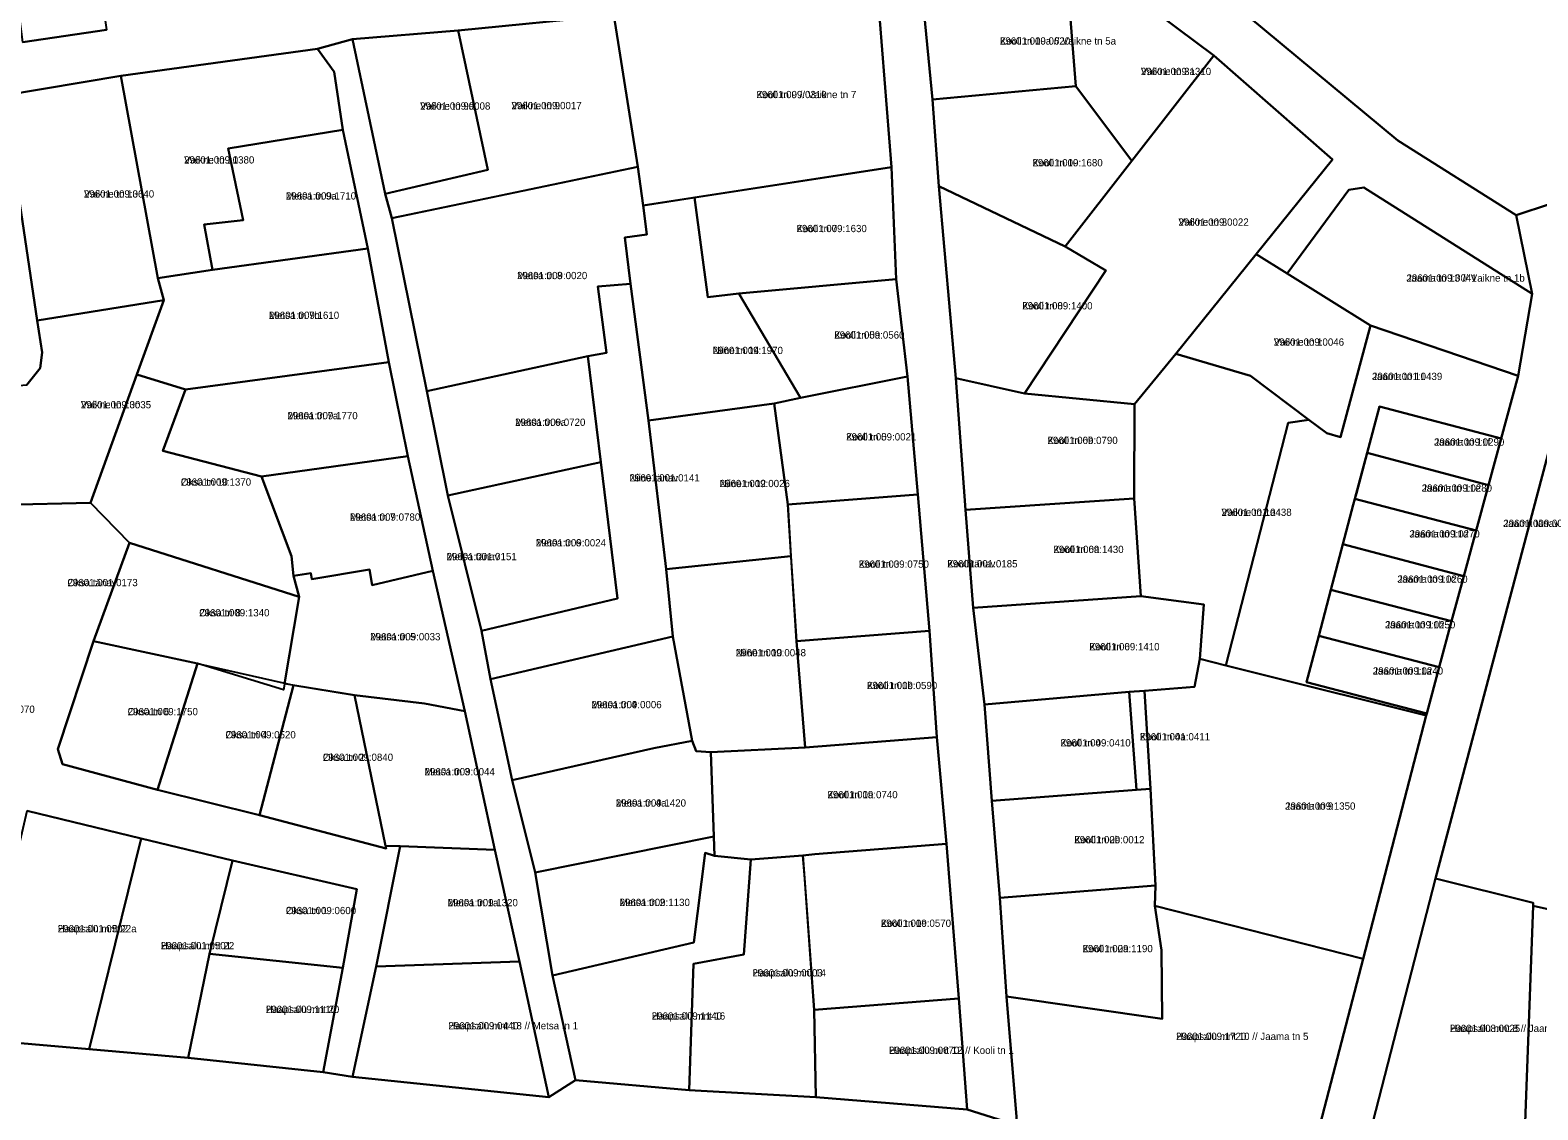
# Model space of a CAD drawing. Extents: x 518839 to 525192, y 6573164 to 6576561.
# Drawn here: x 523365.3 to 523676.7, y 6574443.2 to 6574666.3 of the extents above; entities that cross this region are included whole.
import ezdxf

# ---------------------------------------------------------------- set-up
doc = ezdxf.new("R2010")
doc.units = 0
for name, color, linetype in [('L_AADRESS', 7, 'Continuous'), ('PIIR', 7, 'Continuous'), ('TUNNUS', 7, 'Continuous')]:
    doc.layers.add(name, color=color, linetype=linetype)

msp = doc.modelspace()

# ---------------------------------------------------------------- linework, layer by layer
at = {"layer": 'PIIR'}
for points in [[(523615.35, 6574742.57), (523654.8, 6574704.19), (523668.48, 6574686.53), (523689.46, 6574680.22), (523679.3, 6574630.35), (523672.22, 6574628.03), (523647.77, 6574643.48), (523599.55, 6574683.56), (523607.36, 6574715.71), (523613.69, 6574736.97)], [(523700.2, 6574721.72), (523710.02, 6574696.46), (523687.1, 6574608.01), (523679.27, 6574581.95), (523679.09, 6574579.83), (523655.53, 6574491), (523641.32, 6574435.85), (523645.97, 6574429.03), (523629.03, 6574429.92), (523640.58, 6574474.42), (523653.58, 6574524.69), (523653.71, 6574525.12), (523656.28, 6574534.68), (523658.83, 6574544.16), (523661.39, 6574553.49), (523663.93, 6574562.87), (523666.49, 6574572.3), (523669.1, 6574581.93), (523672.63, 6574594.87), (523675.51, 6574611.76), (523672.22, 6574628.03), (523679.3, 6574630.35), (523689.46, 6574680.22)], [(523371.76, 6574716.56), (523372.55, 6574716.47), (523377.4, 6574692.22), (523381.14, 6574666.32), (523363.81, 6574663.75), (523360.45, 6574690.27), (523354.26, 6574689.99), (523350.61, 6574714.52)], [(523490.79, 6574637.99), (523485.85, 6574669.33), (523540.34, 6574674.35), (523543.19, 6574637.93), (523491.91, 6574630.07)], [(523543.19, 6574637.93), (523540.34, 6574674.35), (523549.77, 6574671.85), (523551.7, 6574651.94), (523552.95, 6574634.06), (523556.48, 6574594.4), (523558.48, 6574567.15), (523560.09, 6574546.96), (523562.38, 6574526.98), (523563.91, 6574507.04), (523565.54, 6574487.01), (523566.98, 6574466.62), (523568.99, 6574441.81), (523569.1, 6574440.03), (523558.83, 6574443.32), (523557.1, 6574466.25), (523554.58, 6574498.15), (523552.58, 6574520.23), (523551.05, 6574542.17), (523548.62, 6574570.34), (523546.53, 6574594.73), (523544.14, 6574614.8)], [(523549.77, 6574671.85), (523579.65, 6574674.61), (523581.29, 6574654.66), (523551.7, 6574651.94)], [(523579.65, 6574674.61), (523590.58, 6574675.41), (523609.74, 6574661.03), (523592.83, 6574639.23), (523586.78, 6574647.32), (523581.29, 6574654.66)], [(523485.85, 6574669.33), (523490.79, 6574637.99), (523461.21, 6574631.85), (523440.01, 6574627.45), (523438.68, 6574632.46), (523459.85, 6574637.41), (523453.75, 6574666.2)], [(523428.15, 6574657.65), (523424.7, 6574662.39), (523431.88, 6574664.38), (523438.68, 6574632.46), (523440.01, 6574627.45), (523447.24, 6574591.66), (523451.59, 6574570.1), (523458.52, 6574542.21), (523460.38, 6574532.19), (523464.9, 6574511.35), (523469.61, 6574492.27), (523473.22, 6574470.97), (523477.93, 6574449.33), (523472.47, 6574445.83), (523466.39, 6574473.87), (523461.27, 6574496.95), (523455.09, 6574525.6), (523448.46, 6574554.54), (523443.35, 6574578.26), (523439.4, 6574597.7), (523435.05, 6574621.16), (523429.94, 6574645.64)], [(523438.68, 6574632.46), (523431.88, 6574664.38), (523453.75, 6574666.2), (523459.85, 6574637.41)], [(523424.7, 6574662.39), (523428.15, 6574657.65), (523429.94, 6574645.64), (523406.24, 6574641.78), (523409.33, 6574627), (523401.26, 6574626.1), (523402.98, 6574616.72), (523391.71, 6574615.04), (523384.07, 6574656.83)], [(523634.25, 6574639.55), (523618.49, 6574619.99), (523601.94, 6574599.41), (523593.37, 6574589.02), (523570.68, 6574591.23), (523587.46, 6574616.6), (523579.04, 6574621.57), (523592.83, 6574639.23), (523609.74, 6574661.03)], [(523384.07, 6574656.83), (523391.71, 6574615.04), (523392.97, 6574610.47), (523366.8, 6574606.26), (523359.93, 6574652.76)], [(523551.7, 6574651.94), (523581.29, 6574654.66), (523586.78, 6574647.32), (523592.83, 6574639.23), (523579.04, 6574621.57), (523552.95, 6574634.06)], [(523401.26, 6574626.1), (523409.33, 6574627), (523406.24, 6574641.78), (523429.94, 6574645.64), (523435.05, 6574621.16), (523402.98, 6574616.72)], [(523440.01, 6574627.45), (523490.79, 6574637.99), (523491.91, 6574630.07), (523492.66, 6574624.04), (523488.16, 6574623.45), (523489.32, 6574613.87), (523482.55, 6574613.28), (523484.36, 6574599.61), (523480.52, 6574598.93), (523447.24, 6574591.66)], [(523544.14, 6574614.8), (523511.65, 6574611.85), (523505.28, 6574611.13), (523502.5, 6574631.69), (523543.19, 6574637.93)], [(523552.95, 6574634.06), (523579.04, 6574621.57), (523587.46, 6574616.6), (523570.68, 6574591.23), (523556.48, 6574594.4)], [(523624.92, 6574615.99), (523637.63, 6574633.25), (523640.7, 6574633.75), (523675.51, 6574611.76), (523672.63, 6574594.87), (523642.14, 6574605.25)], [(523489.32, 6574613.87), (523488.16, 6574623.45), (523492.66, 6574624.04), (523491.91, 6574630.07), (523502.5, 6574631.69), (523505.28, 6574611.13), (523511.65, 6574611.85), (523524.41, 6574590.29), (523518.94, 6574589.17), (523493, 6574585.65)], [(523439.4, 6574597.7), (523397.42, 6574592.05), (523387.38, 6574595.16), (523392.97, 6574610.47), (523391.71, 6574615.04), (523402.98, 6574616.72), (523435.05, 6574621.16)], [(523618.49, 6574619.99), (523624.92, 6574615.99), (523642.14, 6574605.25), (523635.91, 6574582.17), (523633.09, 6574583.01), (523629.38, 6574585.75), (523617.33, 6574594.83), (523601.94, 6574599.41)], [(523484.36, 6574599.61), (523482.55, 6574613.28), (523489.32, 6574613.87), (523493, 6574585.65), (523496.69, 6574554.93), (523498.08, 6574541.03), (523460.38, 6574532.19), (523458.52, 6574542.21), (523486.6, 6574548.87), (523483.21, 6574577.03), (523480.52, 6574598.93)], [(523524.41, 6574590.29), (523511.65, 6574611.85), (523544.14, 6574614.8), (523546.53, 6574594.73)], [(523366.8, 6574606.26), (523392.97, 6574610.47), (523387.38, 6574595.16), (523377.83, 6574568.61), (523360.01, 6574568.22), (523358.68, 6574586.91), (523360.51, 6574592.67), (523364.67, 6574593.01), (523367.38, 6574596.44), (523367.82, 6574599.7)], [(523625.11, 6574585.12), (523629.38, 6574585.75), (523633.09, 6574583.01), (523635.91, 6574582.17), (523642.14, 6574605.25), (523672.63, 6574594.87), (523669.1, 6574581.93), (523643.95, 6574588.55), (523641.4, 6574578.96), (523639.21, 6574570.61), (523638.89, 6574569.43), (523638.54, 6574568.17), (523636.4, 6574560.05), (523633.93, 6574550.67), (523631.42, 6574541.17), (523628.92, 6574531.57), (523653.71, 6574525.12), (523653.58, 6574524.69), (523618.59, 6574533.4), (523612.23, 6574535)], [(523447.24, 6574591.66), (523480.52, 6574598.93), (523483.21, 6574577.03), (523451.59, 6574570.1)], [(523593.37, 6574589.02), (523601.94, 6574599.41), (523617.33, 6574594.83), (523629.38, 6574585.75), (523625.11, 6574585.12), (523612.23, 6574535), (523606.86, 6574536.39), (523607.72, 6574547.61), (523594.71, 6574549.33), (523593.28, 6574569.54)], [(523377.83, 6574568.61), (523387.38, 6574595.16), (523397.42, 6574592.05), (523392.72, 6574579.39), (523413.12, 6574574.05), (523419.31, 6574557.59), (523419.75, 6574553.51), (523420.88, 6574549.17), (523385.87, 6574560.33)], [(523392.72, 6574579.39), (523397.42, 6574592.05), (523439.4, 6574597.7), (523443.35, 6574578.26), (523413.12, 6574574.05)], [(523548.62, 6574570.34), (523521.82, 6574568.26), (523518.94, 6574589.17), (523524.41, 6574590.29), (523546.53, 6574594.73)], [(523570.68, 6574591.23), (523593.37, 6574589.02), (523593.28, 6574569.54), (523558.48, 6574567.15), (523556.48, 6574594.4)], [(523493, 6574585.65), (523518.94, 6574589.17), (523521.82, 6574568.26), (523522.44, 6574557.62), (523496.69, 6574554.93)], [(523641.4, 6574578.96), (523643.95, 6574588.55), (523669.1, 6574581.93), (523666.49, 6574572.3)], [(523679.09, 6574579.83), (523715.18, 6574570.22), (523730.41, 6574491.16), (523690.47, 6574482.07), (523675.73, 6574485.36), (523675.69, 6574485.98), (523655.53, 6574491)], [(523413.12, 6574574.05), (523443.35, 6574578.26), (523448.46, 6574554.54), (523435.97, 6574551.59), (523435.39, 6574554.83), (523423.52, 6574552.87), (523423.32, 6574554.1), (523419.75, 6574553.51), (523419.31, 6574557.59)], [(523483.21, 6574577.03), (523486.6, 6574548.87), (523458.52, 6574542.21), (523451.59, 6574570.1)], [(523638.89, 6574569.43), (523641.4, 6574578.96), (523666.49, 6574572.3), (523663.93, 6574562.87)], [(523521.82, 6574568.26), (523548.62, 6574570.34), (523551.05, 6574542.17), (523523.56, 6574540.02)], [(523593.28, 6574569.54), (523594.71, 6574549.33), (523560.09, 6574546.96), (523558.48, 6574567.15)], [(523636.4, 6574560.05), (523638.54, 6574568.17), (523638.89, 6574569.43), (523663.93, 6574562.87), (523661.39, 6574553.49)], [(523420.88, 6574549.17), (523417.69, 6574530.02), (523399.88, 6574535.41), (523378.41, 6574540.03), (523385.87, 6574560.33)], [(523633.93, 6574550.67), (523636.4, 6574560.05), (523661.39, 6574553.49), (523658.83, 6574544.16)], [(523419.75, 6574553.51), (523423.32, 6574554.1), (523423.52, 6574552.87), (523435.39, 6574554.83), (523435.97, 6574551.59), (523448.46, 6574554.54), (523455.09, 6574525.6), (523446.8, 6574527.14), (523432.3, 6574528.91), (523417.89, 6574531.25), (523420.88, 6574549.17)], [(523522.44, 6574557.62), (523523.56, 6574540.02), (523525.39, 6574518.1), (523505.9, 6574517.13), (523502.87, 6574517.3), (523502.02, 6574519.47), (523498.08, 6574541.03), (523496.69, 6574554.93)], [(523560.09, 6574546.96), (523594.71, 6574549.33), (523607.72, 6574547.61), (523606.86, 6574536.39), (523605.79, 6574530.64), (523595.41, 6574529.79), (523592.27, 6574529.55), (523562.38, 6574526.98)], [(523631.42, 6574541.17), (523633.93, 6574550.67), (523658.83, 6574544.16), (523656.28, 6574534.68)], [(523523.56, 6574540.02), (523551.05, 6574542.17), (523552.58, 6574520.23), (523525.39, 6574518.1)], [(523399.88, 6574535.41), (523391.65, 6574509.31), (523372.04, 6574514.61), (523371.07, 6574517.7), (523378.41, 6574540.03)], [(523460.38, 6574532.19), (523498.08, 6574541.03), (523502.02, 6574519.47), (523494.16, 6574517.95), (523464.9, 6574511.35)], [(523628.92, 6574531.57), (523631.42, 6574541.17), (523656.28, 6574534.68), (523653.71, 6574525.12)], [(523605.79, 6574530.64), (523606.86, 6574536.39), (523612.23, 6574535), (523618.59, 6574533.4), (523653.58, 6574524.69), (523640.58, 6574474.42), (523597.61, 6574485.39), (523597.69, 6574489.54), (523596.69, 6574509.56), (523595.41, 6574529.79)], [(523419.73, 6574530.95), (523412.71, 6574504.1), (523391.65, 6574509.31), (523399.88, 6574535.41)], [(523432.3, 6574528.91), (523438.75, 6574497.74), (523438.86, 6574497.2), (523412.71, 6574504.1), (523419.73, 6574530.95)], [(523593.82, 6574509.34), (523592.27, 6574529.55), (523595.41, 6574529.79), (523596.69, 6574509.56)], [(523432.3, 6574528.91), (523446.8, 6574527.14), (523455.09, 6574525.6), (523461.27, 6574496.95), (523441.74, 6574497.71), (523438.75, 6574497.74)], [(523562.38, 6574526.98), (523592.27, 6574529.55), (523593.82, 6574509.34), (523563.91, 6574507.04)], [(523464.9, 6574511.35), (523494.16, 6574517.95), (523502.02, 6574519.47), (523502.87, 6574517.3), (523505.9, 6574517.13), (523506.49, 6574499.69), (523469.61, 6574492.27)], [(523514.19, 6574494.95), (523506.63, 6574495.69), (523506.49, 6574499.69), (523505.9, 6574517.13), (523525.39, 6574518.1), (523552.58, 6574520.23), (523554.58, 6574498.15), (523527.4, 6574496.01), (523524.91, 6574495.74)], [(523563.91, 6574507.04), (523593.82, 6574509.34), (523596.69, 6574509.56), (523597.69, 6574489.54), (523565.54, 6574487.01)], [(523353.78, 6574457.82), (523364.71, 6574505), (523388.29, 6574499.29), (523377.5, 6574455.78)], [(523377.5, 6574455.78), (523388.29, 6574499.29), (523407.15, 6574494.73), (523402.4, 6574475.46), (523397.99, 6574454)], [(523469.61, 6574492.27), (523506.49, 6574499.69), (523506.63, 6574495.69), (523504.73, 6574496.33), (523502.4, 6574477.82), (523473.22, 6574470.97)], [(523436.76, 6574472.84), (523441.74, 6574497.71), (523461.27, 6574496.95), (523466.39, 6574473.87)], [(523473.22, 6574470.97), (523502.4, 6574477.82), (523504.73, 6574496.33), (523506.63, 6574495.69), (523514.19, 6574494.95), (523512.73, 6574475.34), (523502.3, 6574473.42), (523501.43, 6574447.28), (523477.93, 6574449.33)], [(523502.3, 6574473.42), (523512.73, 6574475.34), (523514.19, 6574494.95), (523524.91, 6574495.74), (523527.22, 6574463.9), (523527.59, 6574445.88), (523501.43, 6574447.28)], [(523527.4, 6574496.01), (523554.58, 6574498.15), (523557.1, 6574466.25), (523527.22, 6574463.9), (523525.23, 6574491.75), (523524.91, 6574495.74)], [(523407.15, 6574494.73), (523432.82, 6574488.8), (523429.89, 6574472.57), (523402.4, 6574475.46)], [(523565.54, 6574487.01), (523597.69, 6574489.54), (523597.61, 6574485.39), (523598.96, 6574476.23), (523599.09, 6574462.04), (523566.98, 6574466.62)], [(523655.53, 6574491), (523675.69, 6574485.98), (523675.73, 6574485.36), (523673.58, 6574427.58), (523645.97, 6574429.03), (523641.32, 6574435.85)], [(523581.36, 6574439.99), (523581.08, 6574438.42), (523569.1, 6574440.03), (523568.99, 6574441.81), (523566.98, 6574466.62), (523599.09, 6574462.04), (523598.96, 6574476.23), (523597.61, 6574485.39), (523640.58, 6574474.42), (523629.03, 6574429.92), (523621.69, 6574430.98), (523607.89, 6574436.58)], [(523673.58, 6574427.58), (523675.73, 6574485.36), (523690.47, 6574482.07), (523690.04, 6574449.11), (523691.03, 6574449.13), (523690.95, 6574439.29), (523696.07, 6574437.5), (523696.24, 6574428.38)], [(523402.4, 6574475.46), (523429.89, 6574472.57), (523425.84, 6574451.01), (523397.99, 6574454)], [(523472.47, 6574445.83), (523431.9, 6574450.04), (523436.76, 6574472.84), (523466.39, 6574473.87)], [(523557.1, 6574466.25), (523558.83, 6574443.32), (523527.59, 6574445.88), (523527.22, 6574463.9)]]:
    msp.add_lwpolyline(points, close=True, dxfattribs=at)
for points in [[(523599.55, 6574683.56), (523647.77, 6574643.48), (523672.22, 6574628.03), (523675.51, 6574611.76), (523640.7, 6574633.75), (523637.63, 6574633.25), (523624.92, 6574615.99), (523618.49, 6574619.99), (523634.25, 6574639.55), (523609.74, 6574661.03), (523590.58, 6574675.41)], [(523485.85, 6574669.33), (523453.75, 6574666.2), (523431.88, 6574664.38), (523424.7, 6574662.39), (523384.07, 6574656.83), (523359.93, 6574652.76)], [(523363.81, 6574663.75), (523381.14, 6574666.32)], [(523359.93, 6574652.76), (523366.8, 6574606.26), (523367.82, 6574599.7), (523367.38, 6574596.44), (523364.67, 6574593.01)], [(523360.01, 6574568.22), (523377.83, 6574568.61), (523385.87, 6574560.33), (523378.41, 6574540.03), (523371.07, 6574517.7), (523372.04, 6574514.61), (523391.65, 6574509.31), (523412.71, 6574504.1), (523438.86, 6574497.2), (523438.75, 6574497.74), (523441.74, 6574497.71), (523436.76, 6574472.84), (523431.9, 6574450.04), (523425.84, 6574451.01), (523429.89, 6574472.57), (523432.82, 6574488.8), (523407.15, 6574494.73), (523388.29, 6574499.29), (523364.71, 6574505)], [(523353.78, 6574457.82), (523377.5, 6574455.78), (523397.99, 6574454), (523425.84, 6574451.01), (523431.9, 6574450.04), (523472.47, 6574445.83), (523477.93, 6574449.33), (523501.43, 6574447.28), (523527.59, 6574445.88), (523558.83, 6574443.32), (523569.1, 6574440.03), (523581.08, 6574438.42), (523581.36, 6574439.99), (523607.89, 6574436.58), (523621.69, 6574430.98), (523629.03, 6574429.92), (523645.97, 6574429.03), (523673.58, 6574427.58), (523696.24, 6574428.38)]]:
    msp.add_lwpolyline(points, dxfattribs=at)

# ---------------------------------------------------------------- texts
at = {"layer": 'L_AADRESS'}
for s, p in [('Kooli tn 10a // Vaikne tn 5a', (523565.59, 6574663.28)), ('Vaikne tn 3a', (523594.7, 6574656.98)), ('Vaikne tn 9a', (523445.87, 6574649.84)), ('Vaikne tn 9', (523464.73, 6574649.93)), ('Kooli tn 9 // Vaikne tn 7', (523515.31, 6574652.21)), ('Vaikne tn 11', (523397.13, 6574638.71)), ('Kooli tn 10', (523572.31, 6574638.12)), ('Vaikne tn 13', (523376.45, 6574631.68)), ('Metsa tn 9a', (523418.15, 6574631.27)), ('Vaikne tn 3', (523602.46, 6574625.86)), ('Kooli tn 7', (523523.6, 6574624.53)), ('Metsa tn 8', (523465.88, 6574614.82)), ('Jaama tn 13 // Vaikne tn 1b', (523649.54, 6574614.31)), ('Metsa tn 7b', (523414.65, 6574606.61)), ('Kooli tn 8', (523570.21, 6574608.57)), ('Kooli tn 5a', (523531.38, 6574602.54)), ('Vaikne tn 1', (523622.15, 6574601.08)), ('Niine tn 14', (523506.28, 6574599.35)), ('Jaama tn 11', (523642.43, 6574593.99)), ('Vaikne tn 13c', (523375.82, 6574588.14)), ('Metsa tn 7a', (523418.47, 6574585.88)), ('Metsa tn 6a', (523465.49, 6574584.52)), ('Kooli tn 5', (523533.83, 6574581.5)), ('Kooli tn 6b', (523575.41, 6574580.77)), ('Jaama tn 11f', (523655.24, 6574580.43)), ('Oksa tn 10', (523396.47, 6574572.17)), ('Niine tänav', (523489.1, 6574573.03)), ('Niine tn 12', (523507.72, 6574571.86)), ('Jaama tn 11e', (523652.7, 6574570.92)), ('Vaikne tn 1a', (523611.33, 6574565.92)), ('Metsa tn 7', (523431.39, 6574564.93)), ('Jaama tänav', (523669.53, 6574563.63)), ('Metsa tn 6', (523469.75, 6574559.62)), ('Jaama tn 11d', (523650.16, 6574561.46)), ('Metsa tänav', (523451.32, 6574556.77)), ('Kooli tn 6a', (523576.63, 6574558.25)), ('Kooli tn 3', (523536.43, 6574555.21)), ('Kooli tänav', (523554.72, 6574555.28)), ('Oksa tänav', (523373.05, 6574551.4)), ('Jaama tn 11c', (523647.66, 6574552.11)), ('Oksa tn 8', (523400.26, 6574545.17)), ('Jaama tn 11b', (523645.12, 6574542.68)), ('Metsa tn 5', (523435.56, 6574540.21)), ('Kooli tn 6', (523584.05, 6574538.15)), ('Niine tn 10', (523511.04, 6574536.91)), ('Jaama tn 11a', (523642.6, 6574533.15)), ('Kooli tn 1b', (523538.14, 6574530.14)), ('Metsa tn 4', (523481.24, 6574526.19)), ('Oksa tn 6', (523385.48, 6574524.74)), ('Oksa tn 4', (523405.69, 6574519.97)), ('Kooli tn 4a', (523594.48, 6574519.55)), ('Kooli tn 4', (523578.09, 6574518.29)), ('Oksa tn 2', (523425.79, 6574515.31)), ('Metsa tn 3', (523446.79, 6574512.33)), ('Kooli tn 1a', (523529.97, 6574507.59)), ('Metsa tn 4a', (523486.27, 6574505.87)), ('Jaama tn 9', (523624.49, 6574505.23)), ('Kooli tn 2b', (523580.94, 6574498.29)), ('Metsa tn 1a', (523451.55, 6574485.28)), ('Metsa tn 2', (523487.07, 6574485.33)), ('Oksa tn 1', (523418.15, 6574483.65)), ('Haapsalu mnt 22a', (523371.04, 6574479.9)), ('Kooli tn 1c', (523541, 6574481.03)), ('Haapsalu mnt 22', (523392.32, 6574476.4)), ('Kooli tn 2a', (523582.65, 6574475.79)), ('Haapsalu mnt 14', (523514.51, 6574470.78)), ('Haapsalu mnt 20', (523414.01, 6574463.24)), ('Haapsalu mnt 18 // Metsa tn 1', (523451.71, 6574459.85)), ('Haapsalu mnt 16', (523493.7, 6574461.87)), ('Haapsalu mnt 10 // Jaama tn 5', (523601.97, 6574457.66)), ('Haapsalu mnt 8 // Jaama tn 8', (523658.52, 6574459.31)), ('Haapsalu mnt 12 // Kooli tn 1', (523542.69, 6574454.79))]:
    msp.add_text(s, height=1.5, dxfattribs=at).set_placement(p)
at = {"layer": 'TUNNUS'}
for s, p in [('29601:009:0620', (523565.59, 6574663.28)), ('29601:009:1310', (523594.7, 6574656.98)), ('29601:009:0008', (523445.87, 6574649.84)), ('29601:009:0017', (523464.73, 6574649.93)), ('29601:009:0310', (523515.31, 6574652.21)), ('29601:009:0380', (523397.13, 6574638.71)), ('29601:009:1680', (523572.31, 6574638.12)), ('29601:009:0640', (523376.45, 6574631.68)), ('29601:009:1710', (523418.15, 6574631.27)), ('29601:009:0022', (523602.46, 6574625.86)), ('29601:009:1630', (523523.6, 6574624.53)), ('29601:009:0020', (523465.88, 6574614.82)), ('29601:009:0041', (523649.54, 6574614.31)), ('29601:009:1610', (523414.65, 6574606.61)), ('29601:009:1400', (523570.21, 6574608.57)), ('29601:009:0560', (523531.38, 6574602.54)), ('29601:009:0046', (523622.15, 6574601.08)), ('29601:009:1970', (523506.28, 6574599.35)), ('29601:001:0439', (523642.43, 6574593.99)), ('29601:009:0035', (523375.82, 6574588.14)), ('29601:009:1770', (523418.47, 6574585.88)), ('29601:009:0720', (523465.49, 6574584.52)), ('29601:009:0021', (523533.83, 6574581.5)), ('29601:009:0790', (523575.41, 6574580.77)), ('29601:009:0290', (523655.24, 6574580.43)), ('29601:009:1370', (523396.47, 6574572.17)), ('29601:001:0141', (523489.1, 6574573.03)), ('29601:009:0026', (523507.72, 6574571.86)), ('29601:009:0280', (523652.7, 6574570.92)), ('29601:001:0438', (523611.33, 6574565.92)), ('29601:009:0780', (523431.39, 6574564.93)), ('29601:009:0058', (523669.53, 6574563.63)), ('29601:009:0024', (523469.75, 6574559.62)), ('29601:009:0270', (523650.16, 6574561.46)), ('29601:001:0151', (523451.32, 6574556.77)), ('29601:009:1430', (523576.63, 6574558.25)), ('29601:009:0750', (523536.43, 6574555.21)), ('29601:001:0185', (523554.72, 6574555.28)), ('29601:001:0173', (523373.05, 6574551.4)), ('29601:009:0260', (523647.66, 6574552.11)), ('29601:009:1340', (523400.26, 6574545.17)), ('29601:009:0250', (523645.12, 6574542.68)), ('29601:009:0033', (523435.56, 6574540.21)), ('29601:009:1410', (523584.05, 6574538.15)), ('29601:009:0048', (523511.04, 6574536.91)), ('29601:009:0240', (523642.6, 6574533.15)), ('29601:009:0590', (523538.14, 6574530.14)), ('29601:009:1070', (523351.79, 6574525.24)), ('29601:009:0006', (523481.24, 6574526.19)), ('29601:009:1750', (523385.48, 6574524.74)), ('29601:009:0520', (523405.69, 6574519.97)), ('29601:001:0411', (523594.48, 6574519.55)), ('29601:009:0410', (523578.09, 6574518.29)), ('29601:009:0840', (523425.79, 6574515.31)), ('29601:009:0044', (523446.79, 6574512.33)), ('29601:009:0740', (523529.97, 6574507.59)), ('29601:009:1420', (523486.27, 6574505.87)), ('29601:009:1350', (523624.49, 6574505.23)), ('29601:009:0012', (523580.94, 6574498.29)), ('29601:009:1320', (523451.55, 6574485.28)), ('29601:009:1130', (523487.07, 6574485.33)), ('29601:009:0600', (523418.15, 6574483.65)), ('29601:001:0502', (523371.04, 6574479.9)), ('29601:009:0570', (523541, 6574481.03)), ('29601:001:0501', (523392.32, 6574476.4)), ('29601:009:1190', (523582.65, 6574475.79)), ('29601:009:0003', (523514.51, 6574470.78)), ('29601:009:1110', (523414.01, 6574463.24)), ('29601:009:0440', (523451.71, 6574459.85)), ('29601:009:1140', (523493.7, 6574461.87)), ('29601:009:1720', (523601.97, 6574457.66)), ('29601:008:0025', (523658.52, 6574459.31)), ('29601:009:0670', (523542.69, 6574454.79))]:
    msp.add_text(s, height=1.5, dxfattribs=at).set_placement(p)

doc.saveas('drawing.dxf')
